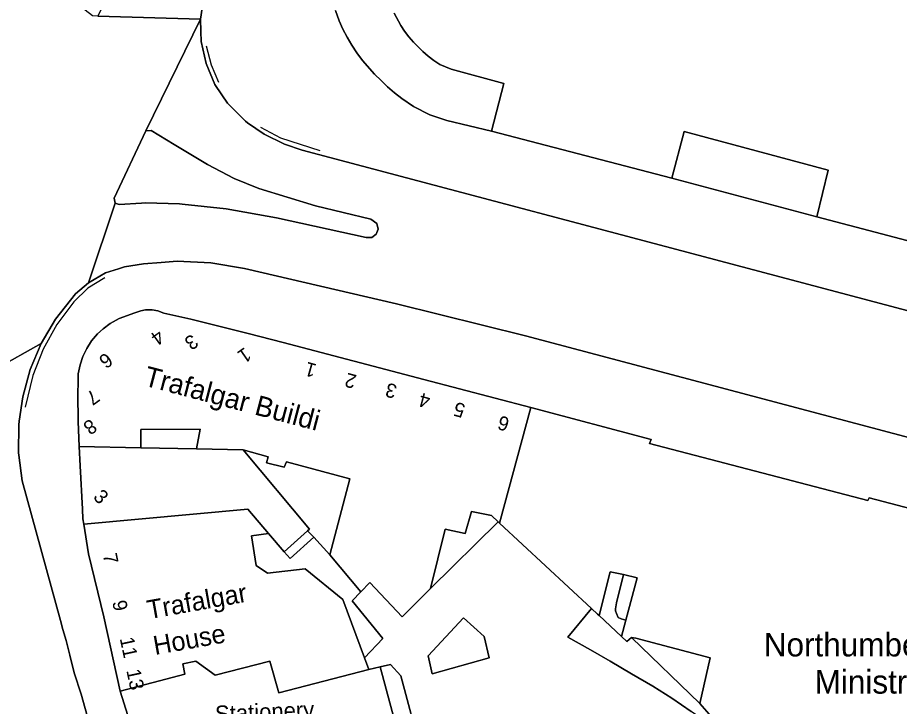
# Model space of a CAD drawing. Extents: x 529240 to 530363, y 179600 to 180767.
# Drawn here: x 530056.2 to 530149.8, y 180323 to 180396.1 of the extents above; entities that cross this region are included whole.
import ezdxf

# ---------------------------------------------------------------- set-up
doc = ezdxf.new("R2010")
doc.units = 0
for name, color, linetype in [('Building', 7, 'Continuous'), ('General surface', 7, 'Continuous'), ('Road Or Track', 7, 'Continuous'), ('Roadside', 7, 'Continuous'), ('Unclassified', 7, 'Continuous')]:
    doc.layers.add(name, color=color, linetype=linetype)

msp = doc.modelspace()

# ---------------------------------------------------------------- linework, layer by layer
at = {"layer": 'Building'}
for points in [[(530089.95, 180396.9), (530090.35, 180395.8), (530090.75, 180394.9), (530091.2, 180394.05), (530091.7, 180393.2), (530092.25, 180392.4), (530092.85, 180391.6), (530094.1, 180390.15), (530094.8, 180389.45), (530095.5, 180388.8), (530096.25, 180388.15), (530097, 180387.55), (530098.25, 180386.7), (530100, 180385.8), (530101.8, 180385.2), (530106.55, 180384.1), (530107.85, 180389.15), (530102.25, 180390.65), (530101.05, 180391.15), (530100.4, 180391.6), (530099.8, 180392.05), (530099.25, 180392.55), (530098.25, 180393.55), (530097.75, 180394.1), (530097.3, 180394.7), (530096.9, 180395.3), (530096.2, 180396.6)], [(530089.95, 180396.9), (530090.35, 180395.8), (530090.75, 180394.9), (530091.2, 180394.05), (530091.7, 180393.2), (530092.25, 180392.4), (530092.85, 180391.6), (530094.1, 180390.15), (530094.8, 180389.45), (530095.5, 180388.8), (530096.25, 180388.15), (530097, 180387.55), (530098.25, 180386.7), (530100, 180385.8), (530101.8, 180385.2), (530106.55, 180384.1)], [(530096.2, 180396.6), (530096.9, 180395.3), (530097.3, 180394.7), (530097.75, 180394.1), (530098.25, 180393.55), (530099.25, 180392.55), (530099.8, 180392.05), (530100.4, 180391.6), (530101.05, 180391.15), (530102.25, 180390.65), (530107.85, 180389.15), (530106.55, 180384.1), (530125.7, 180379.1), (530127, 180384.05), (530142.3, 180379.95), (530141.1, 180375), (530155.5, 180371.2)], [(530106.55, 180384.1), (530107.85, 180389.15), (530102.25, 180390.65), (530101.05, 180391.15), (530100.4, 180391.6), (530099.8, 180392.05), (530099.25, 180392.55), (530098.25, 180393.55), (530097.75, 180394.1), (530097.3, 180394.7), (530096.9, 180395.3), (530096.2, 180396.6)], [(530171.5, 180389.3), (530179.95, 180381.05), (530178.05, 180379), (530179.75, 180377.25), (530185.6, 180375.95), (530188.2, 180371.5), (530187, 180366.65), (530182.5, 180364.45), (530177.25, 180365.8), (530174.25, 180370.8), (530170.9, 180371.65), (530169.8, 180367.4), (530155.5, 180371.2), (530141.1, 180375)], [(530125.7, 180379.1), (530106.55, 180384.1)], [(530141.1, 180375), (530142.3, 180379.95), (530127, 180384.05), (530125.7, 180379.1)], [(530125.7, 180379.1), (530141.1, 180375)], [(530110.7, 180354.75), (530099.35, 180357.7), (530084.4, 180361.65), (530080.7, 180362.6), (530074.6, 180364.1), (530071.75, 180364.75), (530071.1, 180365), (530070.5, 180365.1), (530069.8, 180365.1), (530069.3, 180365), (530068.65, 180364.8), (530067, 180364.2), (530066.05, 180363.65), (530065.3, 180363.1), (530064.7, 180362.55), (530064.05, 180361.8), (530063.55, 180361), (530063.15, 180360.15), (530062.85, 180359.25), (530062.65, 180358.3), (530062.65, 180357.45), (530062.6, 180356.2), (530062.65, 180353.25), (530062.75, 180350.6)], [(530163, 180340.85), (530146.65, 180345.15), (530146.5, 180344.85), (530123.3, 180350.9), (530123.5, 180351.35), (530110.7, 180354.75), (530107.4, 180342.45), (530117.15, 180333.4), (530117.8, 180332.8), (530117.95, 180332.65), (530119.15, 180337.3), (530120.55, 180337), (530122, 180336.65), (530120.8, 180332.15), (530120.35, 180330.4), (530120.9, 180329.9), (530121.4, 180330.3), (530121.85, 180330.25), (530129.75, 180328.15), (530128.65, 180323.3), (530129.9, 180321.9)], [(530110.7, 180354.75), (530107.4, 180342.45)], [(530199.5, 180331.25), (530186.2, 180334.75), (530186, 180334.4), (530162.9, 180340.4), (530163, 180340.85), (530146.65, 180345.15), (530146.5, 180344.85), (530123.3, 180350.9), (530123.5, 180351.35), (530110.7, 180354.75)], [(530069.3, 180350.45), (530069.3, 180352.4), (530075.6, 180352.45), (530075.2, 180350.35)], [(530062.75, 180350.6), (530062.85, 180348.55), (530063.1, 180343.95), (530063.15, 180342.9), (530063.25, 180342.35)], [(530069.3, 180350.45), (530062.75, 180350.6)], [(530075.2, 180350.35), (530069.3, 180350.45)], [(530080.15, 180350.25), (530075.2, 180350.35)], [(530080.15, 180350.25), (530087.2, 180341.8), (530087, 180341.65)], [(530089.35, 180339.1), (530091.5, 180347.15), (530084.75, 180348.95), (530084.5, 180348.4), (530082.65, 180348.85), (530082.8, 180349.5), (530080.15, 180350.25)], [(530082.85, 180341.35), (530080.65, 180343.95), (530063.25, 180342.35)], [(530107.25, 180342.6), (530106.55, 180343.25), (530104.4, 180343.7), (530103.75, 180341.35), (530101.6, 180341.8), (530100.05, 180335.5)], [(530063.25, 180342.35), (530063.75, 180339.2), (530065.35, 180332.5), (530067.1, 180324.6)], [(530127.75, 180322.45), (530125.7, 180323.85), (530123.65, 180325.15), (530121.4, 180326.45), (530119.15, 180327.8), (530117.05, 180329), (530114.65, 180330.35), (530117.15, 180333.4), (530107.4, 180342.45), (530107.25, 180342.6), (530100.05, 180335.5), (530097.05, 180332.5), (530093.6, 180336.15), (530092.65, 180335.15), (530091.75, 180334.2), (530095, 180330.2), (530093.05, 180328.15), (530093.5, 180326.9), (530094.7, 180327.2), (530095.8, 180327.45), (530096.9, 180326.25), (530099.05, 180318.15)], [(530100.05, 180335.5), (530107.25, 180342.6)], [(530107.4, 180342.45), (530107.25, 180342.6)], [(530117.15, 180333.4), (530107.4, 180342.45)], [(530087, 180341.65), (530084.5, 180339.4)], [(530093.05, 180328.15), (530090.75, 180334.35), (530086.75, 180337.6), (530082.75, 180337.15), (530081.55, 180337.95), (530081.05, 180341.1), (530082.85, 180341.35)], [(530084.5, 180339.4), (530082.85, 180341.35)], [(530092.65, 180335.15), (530089.35, 180339.1)], [(530120.55, 180337), (530119.15, 180337.3), (530117.95, 180332.65)], [(530120.8, 180332.15), (530120.3, 180332.3), (530120, 180332.45), (530119.8, 180332.85), (530119.7, 180333.15), (530119.7, 180333.35), (530119.8, 180334), (530120.55, 180337)], [(530120.8, 180332.15), (530122, 180336.65), (530120.55, 180337)], [(530092.65, 180335.15), (530093.6, 180336.15), (530097.05, 180332.5), (530100.05, 180335.5)], [(530093.05, 180328.15), (530095, 180330.2), (530091.75, 180334.2), (530092.65, 180335.15)], [(530138.5, 180300.35), (530136.7, 180305.4), (530131.8, 180319.6), (530131.2, 180319.95), (530129.5, 180321.25), (530127.75, 180322.45), (530125.7, 180323.85), (530123.65, 180325.15), (530121.4, 180326.45), (530119.15, 180327.8), (530117.05, 180329), (530114.65, 180330.35), (530117.15, 180333.4)], [(530117.95, 180332.65), (530117.8, 180332.8), (530117.15, 180333.4)], [(530099.8, 180328.35), (530103.55, 180332.4), (530105.75, 180330.4), (530106.3, 180328.15), (530100.25, 180326.45), (530099.8, 180328.35)], [(530120.35, 180330.4), (530117.95, 180332.65)], [(530120.35, 180330.4), (530120.8, 180332.15)], [(530121.4, 180330.3), (530120.9, 180329.9), (530120.35, 180330.4)], [(530128.65, 180323.3), (530129.75, 180328.15), (530121.85, 180330.25), (530121.4, 180330.3)], [(530093.5, 180326.9), (530083.95, 180324.45), (530083, 180327.8), (530077.2, 180326.3), (530075.15, 180327.8), (530073.75, 180327.5), (530073.95, 180326.4), (530067.1, 180324.6)], [(530093.5, 180326.9), (530093.05, 180328.15)], [(530097.25, 180317.7), (530099.05, 180318.15), (530096.9, 180326.25), (530095.8, 180327.45), (530094.7, 180327.2)], [(530094.7, 180327.2), (530093.5, 180326.9)], [(530094.7, 180327.2), (530097.25, 180317.7)], [(530067.1, 180324.6), (530068.5, 180320.1), (530070.95, 180311.65), (530073.4, 180303.4), (530078.35, 180304.65), (530099.3, 180309.9)], [(530139.4, 180313.3), (530137.45, 180315.15), (530137.85, 180315.85), (530138.05, 180316.4), (530138.2, 180317.15), (530138.4, 180318.8), (530130.45, 180322.1), (530129.9, 180321.9), (530128.65, 180323.3)]]:
    msp.add_lwpolyline(points, dxfattribs=at)
for points in [[(530141.1, 180375), (530142.3, 180379.95), (530127, 180384.05), (530125.7, 180379.1)], [(530062.75, 180350.6), (530069.3, 180350.45), (530069.3, 180352.4), (530075.6, 180352.45), (530075.2, 180350.35), (530080.15, 180350.25), (530082.8, 180349.5), (530082.65, 180348.85), (530084.5, 180348.4), (530084.75, 180348.95), (530091.5, 180347.15), (530089.35, 180339.1), (530092.65, 180335.15), (530093.6, 180336.15), (530097.05, 180332.5), (530100.05, 180335.5), (530101.6, 180341.8), (530103.75, 180341.35), (530104.4, 180343.7), (530106.55, 180343.25), (530107.25, 180342.6), (530107.4, 180342.45), (530110.7, 180354.75), (530099.35, 180357.7), (530084.4, 180361.65), (530080.7, 180362.6), (530074.6, 180364.1), (530071.75, 180364.75), (530071.1, 180365), (530070.5, 180365.1), (530069.8, 180365.1), (530069.3, 180365), (530068.65, 180364.8), (530067, 180364.2), (530066.05, 180363.65), (530065.3, 180363.1), (530064.7, 180362.55), (530064.05, 180361.8), (530063.55, 180361), (530063.15, 180360.15), (530062.85, 180359.25), (530062.65, 180358.3), (530062.65, 180357.45), (530062.6, 180356.2), (530062.65, 180353.25)], [(530069.3, 180350.45), (530062.75, 180350.6), (530062.85, 180348.55), (530063.1, 180343.95), (530063.15, 180342.9), (530063.25, 180342.35), (530080.65, 180343.95), (530082.85, 180341.35), (530084.5, 180339.4), (530087, 180341.65), (530087.2, 180341.8), (530080.15, 180350.25), (530075.2, 180350.35)], [(530093.5, 180326.9), (530093.05, 180328.15), (530090.75, 180334.35), (530086.75, 180337.6), (530082.75, 180337.15), (530081.55, 180337.95), (530081.05, 180341.1), (530082.85, 180341.35), (530080.65, 180343.95), (530063.25, 180342.35), (530063.75, 180339.2), (530065.35, 180332.5), (530067.1, 180324.6), (530073.95, 180326.4), (530073.75, 180327.5), (530075.15, 180327.8), (530077.2, 180326.3), (530083, 180327.8), (530083.95, 180324.45)], [(530120.8, 180332.15), (530120.3, 180332.3), (530120, 180332.45), (530119.8, 180332.85), (530119.7, 180333.15), (530119.7, 180333.35), (530119.8, 180334), (530120.55, 180337), (530119.15, 180337.3), (530117.95, 180332.65), (530120.35, 180330.4)], [(530099.8, 180328.35), (530103.55, 180332.4), (530105.75, 180330.4), (530106.3, 180328.15), (530100.25, 180326.45)], [(530067.1, 180324.6), (530068.5, 180320.1), (530070.95, 180311.65), (530073.4, 180303.4), (530078.35, 180304.65), (530099.3, 180309.9), (530097.25, 180317.7), (530094.7, 180327.2), (530093.5, 180326.9), (530083.95, 180324.45), (530083, 180327.8), (530077.2, 180326.3), (530075.15, 180327.8), (530073.75, 180327.5), (530073.95, 180326.4)], [(530094.7, 180327.2), (530097.25, 180317.7), (530099.05, 180318.15), (530096.9, 180326.25), (530095.8, 180327.45)]]:
    msp.add_lwpolyline(points, close=True, dxfattribs=at)
at = {"layer": 'General surface'}
for points in [[(530075.2, 180350.35), (530075.6, 180352.45), (530069.3, 180352.4), (530069.3, 180350.45)], [(530087.65, 180340.95), (530089.35, 180339.1), (530091.5, 180347.15), (530084.75, 180348.95), (530084.5, 180348.4), (530082.65, 180348.85), (530082.8, 180349.5), (530080.15, 180350.25), (530087.2, 180341.8), (530087, 180341.65)], [(530107.25, 180342.6), (530106.55, 180343.25), (530104.4, 180343.7), (530103.75, 180341.35), (530101.6, 180341.8), (530100.05, 180335.5)], [(530084.5, 180339.4), (530085.15, 180338.7), (530087.65, 180340.95), (530087, 180341.65)], [(530092.65, 180335.15), (530089.35, 180339.1), (530087.65, 180340.95), (530085.15, 180338.7), (530084.5, 180339.4), (530082.85, 180341.35), (530081.05, 180341.1), (530081.55, 180337.95), (530082.75, 180337.15), (530086.75, 180337.6), (530090.75, 180334.35), (530093.05, 180328.15), (530095, 180330.2), (530091.75, 180334.2)], [(530120.8, 180332.15), (530122, 180336.65), (530120.55, 180337), (530119.8, 180334), (530119.7, 180333.35), (530119.7, 180333.15), (530119.8, 180332.85), (530120, 180332.45), (530120.3, 180332.3)], [(530099.8, 180328.35), (530100.25, 180326.45), (530106.3, 180328.15), (530105.75, 180330.4), (530103.55, 180332.4)], [(530128.65, 180323.3), (530129.75, 180328.15), (530121.85, 180330.25), (530121.4, 180330.3)]]:
    msp.add_lwpolyline(points, close=True, dxfattribs=at)
msp.add_lwpolyline([(530129.9, 180321.9), (530128.65, 180323.3), (530121.4, 180330.3), (530120.9, 180329.9), (530120.35, 180330.4), (530117.95, 180332.65), (530117.8, 180332.8), (530117.15, 180333.4), (530114.65, 180330.35), (530117.05, 180329), (530119.15, 180327.8), (530121.4, 180326.45), (530123.65, 180325.15), (530125.7, 180323.85), (530127.75, 180322.45)], dxfattribs=at)
at = {"layer": 'Road Or Track'}
msp.add_lwpolyline([(530075.45, 180420.08), (530075.54, 180419.53), (530068.51, 180404.42), (530066.03, 180399.09), (530064.72, 180396.29), (530075.64, 180395.99), (530076, 180398.36), (530076.79, 180400.63), (530080.91, 180407.89), (530084.15, 180412.58), (530087.72, 180417.02), (530085.18, 180423.93)], close=True, dxfattribs=at)
for points in [[(530087.72, 180417.02), (530084.15, 180412.58), (530080.91, 180407.89), (530076.79, 180400.63), (530076, 180398.36), (530075.64, 180395.99)], [(530049.12, 180356.16), (530058.71, 180361.53), (530060.22, 180364.12), (530062.36, 180366.82), (530063.73, 180367.99), (530066.57, 180376.43), (530066.47, 180376.98), (530069.83, 180384.13), (530075.64, 180395.99), (530064.72, 180396.29), (530064.16, 180396.33), (530062.62, 180397.53), (530060.18, 180399.43), (530056.33, 180402.43), (530054.25, 180403.62)], [(530185.76, 180355.74), (530086.41, 180382.08), (530084.54, 180382.7), (530082.39, 180383.76), (530080.63, 180384.98), (530080.42, 180385.13), (530078.49, 180387.05), (530077.9, 180387.95), (530077.17, 180389.05), (530076.23, 180391.26), (530075.71, 180393.6), (530075.68, 180394.65), (530075.64, 180395.99), (530069.83, 180384.13), (530070.4, 180384.16), (530072.84, 180382.68), (530076.02, 180380.74), (530076.39, 180380.55), (530079.2, 180379.05), (530081.83, 180378.01), (530087.84, 180376.14), (530093.71, 180374.73), (530094.37, 180374.26), (530094.51, 180373.69), (530094.3, 180373.14), (530093.81, 180372.8), (530093.22, 180372.8), (530083.69, 180374.87), (530078.37, 180375.82), (530073.68, 180376.34), (530073.4, 180376.37), (530069.8, 180376.46), (530069.37, 180376.43), (530066.98, 180376.28), (530066.57, 180376.43), (530063.73, 180367.99), (530065.55, 180369.03), (530066.93, 180369.47), (530067.55, 180369.66), (530069.56, 180370), (530071.44, 180370.14), (530073.15, 180370.26), (530076.74, 180370.09), (530080.29, 180369.49), (530096.45, 180365.76), (530110.13, 180362.34), (530186.04, 180342.22)], [(530075.64, 180395.99), (530075.68, 180394.65), (530075.71, 180393.6), (530076.23, 180391.26), (530077.17, 180389.05), (530077.9, 180387.95), (530078.49, 180387.05), (530080.42, 180385.13), (530080.63, 180384.98), (530082.39, 180383.76), (530084.54, 180382.7), (530086.41, 180382.08), (530185.76, 180355.74)], [(530069.83, 180384.13), (530066.47, 180376.98), (530066.57, 180376.43)], [(530066.57, 180376.43), (530066.98, 180376.28), (530069.37, 180376.43), (530069.8, 180376.46), (530073.4, 180376.37), (530073.68, 180376.34), (530078.37, 180375.82), (530083.69, 180374.87), (530093.22, 180372.8), (530093.81, 180372.8), (530094.3, 180373.14), (530094.51, 180373.69), (530094.37, 180374.26), (530093.71, 180374.73), (530087.84, 180376.14), (530081.83, 180378.01), (530079.2, 180379.05), (530076.39, 180380.55), (530076.02, 180380.74), (530072.84, 180382.68), (530070.4, 180384.16), (530069.83, 180384.13)], [(530063.73, 180367.99), (530065.55, 180369.03), (530066.93, 180369.47), (530067.55, 180369.66), (530069.56, 180370), (530071.44, 180370.14), (530073.15, 180370.26), (530076.74, 180370.09), (530080.29, 180369.49), (530096.45, 180365.76), (530110.13, 180362.34), (530186.04, 180342.22)], [(530058.71, 180361.53), (530060.22, 180364.12), (530062.36, 180366.82), (530063.73, 180367.99)], [(530054.93, 180301.48), (530067.51, 180308.15), (530066.75, 180310.85), (530065.3, 180316.05), (530064.05, 180320.35), (530062.95, 180324.3), (530062.2, 180326.55), (530061.75, 180328.45), (530061.35, 180330), (530061, 180331.15), (530060.78, 180332.1), (530056.68, 180346.94), (530056.34, 180349.67), (530056.31, 180349.91), (530056.34, 180352.91), (530056.39, 180353.29), (530056.75, 180355.88), (530057.54, 180358.77), (530058.71, 180361.53), (530049.12, 180356.16)], [(530058.71, 180361.53), (530057.54, 180358.77), (530056.75, 180355.88), (530056.39, 180353.29), (530056.34, 180352.91), (530056.31, 180349.91), (530056.34, 180349.67), (530056.68, 180346.94), (530060.78, 180332.1), (530061, 180331.15), (530061.35, 180330), (530061.75, 180328.45), (530062.2, 180326.55), (530062.95, 180324.3), (530064.05, 180320.35), (530065.3, 180316.05), (530066.75, 180310.85), (530067.51, 180308.15)]]:
    msp.add_lwpolyline(points, dxfattribs=at)
at = {"layer": 'Roadside'}
for points in [[(530076, 180398.36), (530075.64, 180395.99), (530075.68, 180394.65), (530075.71, 180393.6), (530076.23, 180391.26), (530077.17, 180389.05), (530077.9, 180387.95), (530078.49, 180387.05), (530080.42, 180385.13), (530080.63, 180384.98), (530082.39, 180383.76), (530084.54, 180382.7), (530086.41, 180382.08), (530185.76, 180355.74)], [(530155.5, 180371.2), (530141.1, 180375), (530125.7, 180379.1), (530106.55, 180384.1), (530101.8, 180385.2), (530100, 180385.8), (530098.25, 180386.7), (530097, 180387.55), (530096.25, 180388.15), (530095.5, 180388.8), (530094.8, 180389.45), (530094.1, 180390.15), (530092.85, 180391.6), (530092.25, 180392.4), (530091.7, 180393.2), (530091.2, 180394.05), (530090.75, 180394.9), (530090.35, 180395.8), (530089.95, 180396.9)], [(530186.04, 180342.22), (530110.13, 180362.34), (530096.45, 180365.76), (530080.29, 180369.49), (530076.74, 180370.09), (530073.15, 180370.26), (530071.44, 180370.14), (530069.56, 180370), (530067.55, 180369.66), (530066.93, 180369.47), (530065.55, 180369.03), (530063.73, 180367.99), (530062.36, 180366.82), (530060.22, 180364.12), (530058.71, 180361.53), (530057.54, 180358.77), (530056.75, 180355.88), (530056.39, 180353.29), (530056.34, 180352.91), (530056.31, 180349.91), (530056.34, 180349.67), (530056.68, 180346.94), (530060.78, 180332.1), (530061, 180331.15), (530061.35, 180330), (530061.75, 180328.45), (530062.2, 180326.55), (530062.95, 180324.3), (530064.05, 180320.35)], [(530068.5, 180320.1), (530067.1, 180324.6), (530065.35, 180332.5), (530063.75, 180339.2), (530063.25, 180342.35), (530063.15, 180342.9), (530063.1, 180343.95), (530062.85, 180348.55), (530062.75, 180350.6), (530062.65, 180353.25), (530062.6, 180356.2), (530062.65, 180357.45), (530062.65, 180358.3), (530062.85, 180359.25), (530063.15, 180360.15), (530063.55, 180361), (530064.05, 180361.8), (530064.7, 180362.55), (530065.3, 180363.1), (530066.05, 180363.65), (530067, 180364.2), (530068.65, 180364.8), (530069.3, 180365), (530069.8, 180365.1), (530070.5, 180365.1), (530071.1, 180365), (530071.75, 180364.75), (530074.6, 180364.1), (530080.7, 180362.6), (530084.4, 180361.65), (530099.35, 180357.7), (530110.7, 180354.75), (530123.5, 180351.35), (530123.3, 180350.9), (530146.5, 180344.85), (530146.65, 180345.15), (530163, 180340.85)]]:
    msp.add_lwpolyline(points, dxfattribs=at)
msp.add_lwpolyline([(530069.83, 180384.13), (530066.47, 180376.98), (530066.57, 180376.43), (530066.98, 180376.28), (530069.37, 180376.43), (530069.8, 180376.46), (530073.4, 180376.37), (530073.68, 180376.34), (530078.37, 180375.82), (530083.69, 180374.87), (530093.22, 180372.8), (530093.81, 180372.8), (530094.3, 180373.14), (530094.51, 180373.69), (530094.37, 180374.26), (530093.71, 180374.73), (530087.84, 180376.14), (530081.83, 180378.01), (530079.2, 180379.05), (530076.39, 180380.55), (530076.02, 180380.74), (530072.84, 180382.68), (530070.4, 180384.16)], close=True, dxfattribs=at)
at = {"layer": 'Unclassified'}
for points in [[(530064.72, 180396.29), (530075.64, 180395.99)], [(530069.83, 180384.13), (530075.64, 180395.99)], [(530076.24, 180393.14), (530076.75, 180391.11), (530077.55, 180389.29)], [(530082.02, 180384.52), (530084.12, 180383.36), (530088.32, 180382.04)], [(530066.57, 180376.43), (530063.73, 180367.99)], [(530065.46, 180368.49), (530063.68, 180367.4), (530062.17, 180365.94), (530060.38, 180363.54), (530058.91, 180360.92), (530057.81, 180358.14), (530057, 180354.77)], [(530049.12, 180356.16), (530058.71, 180361.53)], [(530087, 180341.65), (530087.65, 180340.95)], [(530087.65, 180340.95), (530085.15, 180338.7), (530084.5, 180339.4)], [(530087.65, 180340.95), (530089.35, 180339.1)], [(530128.65, 180323.3), (530121.4, 180330.3)]]:
    msp.add_lwpolyline(points, dxfattribs=at)

# ---------------------------------------------------------------- texts
for s, height, rotation, p in [('4', 1.5, 216.1, (530071.1, 180363.1)), ('3', 1.5, 215.4, (530074.7, 180362.6)), ('1', 1.5, 214.8, (530080.35, 180361.2)), ('6', 1.5, 216.5, (530065.6, 180360.65)), ('1', 1.5, 164.3, (530088.05, 180359.3)), ('Trafalgar Buildi', 2.125, 345.3, (530069.5, 180357.1)), ('2', 1.5, 165, (530092.3, 180358.15)), ('3', 1.5, 165.2, (530096.6, 180357.1)), ('7', 1.5, 216.1, (530064.2, 180356.75)), ('4', 1.5, 165.1, (530100.15, 180356.05)), ('5', 1.5, 164.5, (530103.85, 180355.05)), ('6', 1.5, 164.1, (530108.55, 180353.6)), ('8', 1.5, 214.9, (530063.95, 180353.6)), ('3', 1.5, 314.4, (530064.15, 180345.15)), ('7', 1.5, 281.5, (530065.25, 180339.1)), ('Trafalgar', 2, 10.1, (530070.15, 180332.25)), ('9', 1.5, 281.8, (530066.25, 180334.1)), ('House', 2, 10.1, (530070.8, 180328.45)), ('11', 1.5, 282, (530067.05, 180330.2)), ('13', 1.5, 282, (530067.75, 180326.8)), ('Stationery', 1.75, 2.7, (530077.22, 180321.3))]:
    msp.add_text(s, height=height, rotation=rotation, dxfattribs=at).set_placement(p)
for s, p in [('Northumberland H', (530135.45, 180328.3)), ('Ministry of Defe', (530140.85, 180324.35))]:
    msp.add_text(s, height=2.5, dxfattribs=at).set_placement(p)

doc.saveas('drawing.dxf')
